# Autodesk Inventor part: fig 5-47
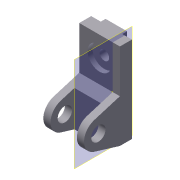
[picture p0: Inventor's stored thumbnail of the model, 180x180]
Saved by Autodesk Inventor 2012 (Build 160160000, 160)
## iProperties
Shininess: 65.0
Angle Display Precision: 2
Document Length Units: 11269
Document Angle Units: 11279
Document Time Units: 11290
Document Mass Units: 11283
Document Length Units Precision: 3
Document Angle Units Precision: 2
Created: 2001-11
Part Number: fig 5-47
Document SubType Name: Modeling
Designer: Renu Muthoo
Density: 1 g/cm^3
Material: Default
Density: 0.0
Volumn: 0.0
Area: 0.0
PropertySet Name: Model Information
Control State: 0
Master: False
Checked Out: False
Author: Renu Muthoo
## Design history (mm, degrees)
node "Sketch1"
sketch "Sketch2"
  geometry: L1 (33.257, 104.664)-(33.257, -75.336); L2 (33.257, -75.336)-(8.257, -75.336); L3 (8.257, -75.336)-(-45.451, -59.045); L4 (-45.451, -1.628)-(8.257, 14.664); L5 (8.257, 14.664)-(8.257, 104.664); L6 (8.257, 104.664)-(33.257, 104.664); C1 r 15 at (-36.743, -30.336); A1 r 30 centre (-36.743, -30.336) between (-45.451, -1.628) and (-45.451, -59.045)
  constraints: 12 end point, 2 centre point, 2 equal length, 2 parallel, 2 point on circle, 2 tangent, 1 coincident, 1 perpendicular, 1 vertical
  dimensions: "d0" = 180 distance of L1.start L1.end; "d1" = 30 radius of A1; "d2" = 25 distance of L5.end L1.start; "d3" = 45 distance from line of L2 A1.centre; "d4" = 70 distance from line of L1 A1.centre; "d5" = 30 diameter of C1
extrude "Extrusion1" new body sketch "Sketch2" distance "d6" = 85; taper "d7" = 0 deg
workplane "Work Plane1"
sketch "Sketch3"
  geometry: L1 (15, 62.364)-(70, 62.364); L2 (70, 62.364)-(70, -52.386); L3 (70, -52.386)-(15, -52.386); L4 (15, -52.386)-(15, 62.364); L5 (0, -45)-(0, -28.708) reference
  constraints: 8 end point, 2 parallel, 1 horizontal, 1 perpendicular
  dimensions: "d8" = 55 distance of L1.start L1.end; "d9" = 15 distance between parallel lines of L5 L4
extrude "Extrusion2" cut sketch "Sketch3" distance "d10" = 50; taper "d11" = 0 deg
sketch "Sketch4"
  geometry: L1 (0, 25)-(85, 25) reference; L2 (0, 0)-(0, 25) reference; L3 (20, 25)-(65, 25); L4 (65, 25)-(65, 35); L5 (65, 35)-(20, 35); L6 (20, 35)-(20, 25)
  constraints: 8 end point, 2 parallel, 1 horizontal, 1 perpendicular, 1 point on line
  dimensions: "d12" = 45 distance of L4.end L5.end; "d13" = 10 distance of L3.end L4.end; "d14" = 20 distance between parallel lines of L2 L6
extrude "Extrusion3" join sketch "Sketch4" stored distance "d15" = 50; taper "d16" = 0 deg
sketch "Sketch5"
  geometry: L1 (85, 0)-(85, 90) reference; L2 (0, 90)-(85, 90) reference; 1 further point
  dimensions: "d17" = 42 distance from line of L2 point (42.5, 48); "d18" = 42.5 distance from line of L1 point (42.5, 48)
hole "Hole1" sketch "Sketch5" at (42.5, 48) diameter "d19" = 20; stored, may be unused: countersink angle "d23" = 82 deg, drill point angle "d25" = 118 deg; dims "d20" = 6, "d21" = 50, "d22" = 10, "d24" = 8
workplane "Work Plane7"
workpoint "Work Point7"
workpoint "Work Point8"
body "Solid1"
other parameters: "d29" = 0
